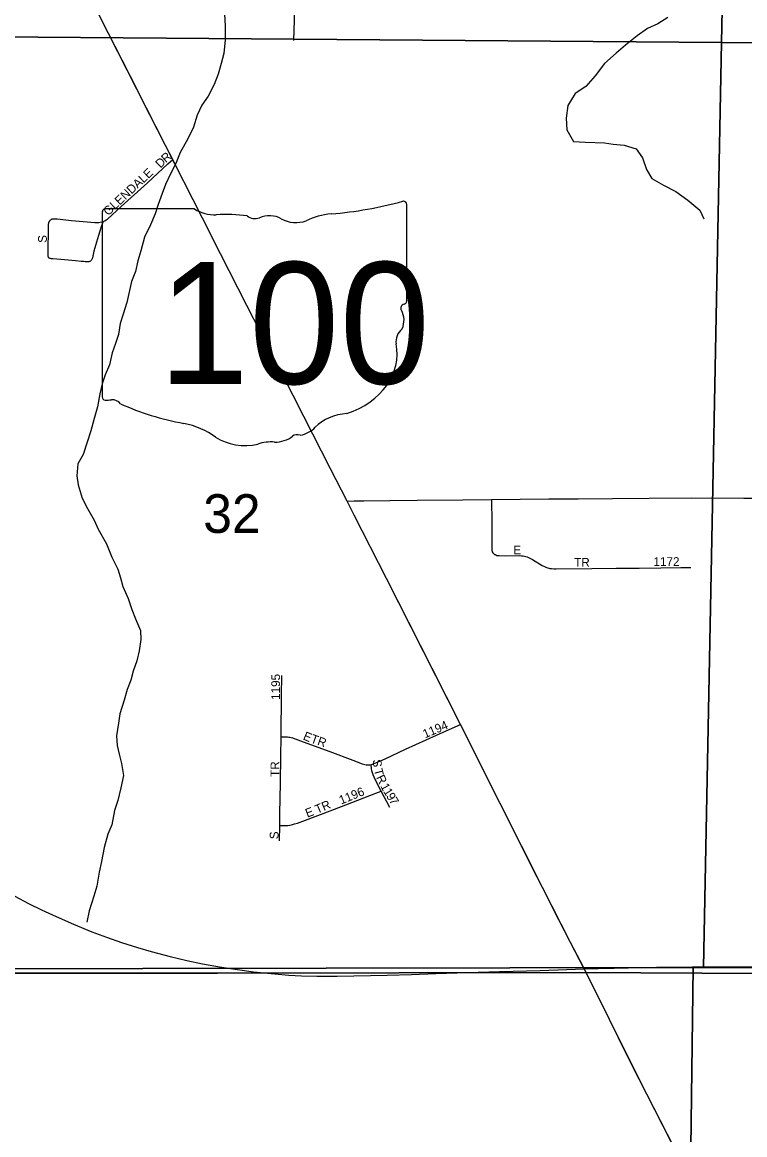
# Model space of a CAD drawing. Extents: x 0 to 34, y 0 to 22.
# Drawn here: x 6.114 to 6.505, y 17.325 to 17.927 of the extents above; entities that cross this region are included whole.
import ezdxf

# ---------------------------------------------------------------- set-up
doc = ezdxf.new("R2010")
doc.units = 0
for name, color, linetype in [('Default', 7, 'Continuous'), ('GM_X_Minor_River', 7, 'Continuous'), ('GM_X_Section', 7, 'Continuous'), ('GM_X_Section_Text', 7, 'Continuous'), ('GM_X_State_Location', 7, 'Continuous'), ('GM_X_State_Route', 7, 'Continuous'), ('GM_X_State_Shield', 7, 'Continuous'), ('GM_X_Township', 7, 'Continuous'), ('GM_X_Township_Road', 7, 'Continuous'), ('GM_X_Township_Subdivision', 7, 'Continuous'), ('GM_X_Township_Subdivision_Text', 7, 'Continuous'), ('GM_X_US_Route', 7, 'Continuous')]:
    doc.layers.add(name, color=color, linetype=linetype)

msp = doc.modelspace()

# ---------------------------------------------------------------- linework, layer by layer
at = {"layer": 'Default'}
for points in [[(6.21175, 17.82109), (6.19182, 17.86034), (6.14526, 17.95216), (6.11969, 18.00306), (6.11076, 18.02099), (6.07084, 18.10026), (6.06147, 18.11896), (6.05496, 18.13197), (6.04884, 18.14072), (6.02545, 18.17135), (6.01014, 18.19175), (5.98748, 18.22193), (5.95849, 18.26057), (5.9573, 18.26217)], [(6.39588, 17.45861), (6.37293, 17.50419), (6.35143, 17.54696), (6.31143, 17.62597), (6.29397, 17.66031), (6.29011, 17.66789), (6.28111, 17.68542), (6.26671, 17.71362)], [(6.41797, 17.41555), (6.41103, 17.42887), (6.39588, 17.45861)], [(6.4784, 17.29558), (6.45232, 17.34668), (6.43203, 17.38715), (6.42213, 17.40718), (6.41883, 17.41387)]]:
    msp.add_lwpolyline(points, dxfattribs=at)
at = {"layer": 'GM_X_Minor_River'}
for points in [[(6.2237, 17.93172), (6.22403, 17.92508), (6.22398, 17.91768), (6.22335, 17.91029), (6.22198, 17.9048), (6.22024, 17.89912), (6.21811, 17.89344), (6.21484, 17.8872), (6.21139, 17.8823), (6.20888, 17.87681), (6.20693, 17.87038), (6.20385, 17.86395), (6.19963, 17.85658), (6.19731, 17.85072), (6.19442, 17.84505), (6.19172, 17.83937), (6.18998, 17.83445), (6.18785, 17.8284), (6.1861, 17.82348), (6.18359, 17.81743), (6.18032, 17.81081), (6.17837, 17.80343), (6.17681, 17.79794), (6.17544, 17.79225), (6.17331, 17.78677), (6.17194, 17.78033), (6.17076, 17.7754), (6.16882, 17.76916), (6.16727, 17.76405), (6.16627, 17.75817), (6.16472, 17.75325), (6.16298, 17.74814), (6.16141, 17.7417), (6.15909, 17.73622), (6.15754, 17.7313), (6.15617, 17.72599), (6.15498, 17.71898), (6.15323, 17.71255), (6.15128, 17.70592), (6.14934, 17.69986), (6.14721, 17.69305), (6.14432, 17.68814), (6.14371, 17.6815), (6.14443, 17.67675), (6.14666, 17.66953), (6.14946, 17.66381), (6.15321, 17.65752), (6.15526, 17.65276), (6.15976, 17.64476), (6.16274, 17.63753), (6.16592, 17.63105), (6.1674, 17.6263), (6.16869, 17.62155), (6.17149, 17.61508), (6.17354, 17.60918), (6.17559, 17.60404), (6.1782, 17.59776), (6.17835, 17.59301), (6.17755, 17.58676), (6.17618, 17.58146), (6.17424, 17.57578), (6.17307, 17.57086), (6.17094, 17.56594), (6.16938, 17.56007), (6.16705, 17.55269), (6.16626, 17.54757), (6.16526, 17.54075), (6.1656, 17.53562)], [(6.4637, 17.92973), (6.45836, 17.92635), (6.45265, 17.92374), (6.44712, 17.9198), (6.44082, 17.91472), (6.43567, 17.91039), (6.42936, 17.90475), (6.42438, 17.89815), (6.41922, 17.8923), (6.4135, 17.88855), (6.40947, 17.88213), (6.40866, 17.87531), (6.40899, 17.86885), (6.41255, 17.86256), (6.41919, 17.86232), (6.42943, 17.86187), (6.43417, 17.86107), (6.44005, 17.86065), (6.44648, 17.8587), (6.45005, 17.85374), (6.45209, 17.84747), (6.45509, 17.84251), (6.46133, 17.83886), (6.46795, 17.83558), (6.47455, 17.83079), (6.48096, 17.82543), (6.48321, 17.82067)], [(6.1656, 17.53562), (6.1667, 17.53087), (6.16799, 17.52574), (6.16909, 17.51928), (6.16752, 17.51265), (6.16595, 17.50584), (6.1642, 17.50035), (6.16263, 17.49258), (6.1605, 17.48747), (6.15855, 17.48028), (6.15717, 17.4727), (6.1558, 17.46702), (6.15461, 17.45944), (6.15305, 17.45395), (6.15052, 17.446), (6.14915, 17.43994)]]:
    msp.add_lwpolyline(points, dxfattribs=at)
at = {"layer": 'GM_X_Section'}
for points in [[(6.50305, 18.41943), (6.4928, 17.91626), (5.98372, 17.92012), (5.99052, 18.41894)], [(6.99984, 18.41775), (6.98884, 17.91553), (6.4928, 17.91626), (6.50305, 18.41943)], [(5.98372, 17.92012), (6.4928, 17.91626), (6.48295, 17.41537), (6.47745, 17.41541), (5.98065, 17.41444), (5.97819, 17.41427)], [(6.98884, 17.91553), (6.97935, 17.41426), (6.48295, 17.41537), (6.4928, 17.91626)], [(5.98065, 17.41444), (6.47745, 17.41541), (6.47069, 16.89897), (6.35343, 16.90099), (6.35585, 17.07131), (5.97596, 17.07021)], [(6.47745, 17.41541), (6.48295, 17.41537), (6.97935, 17.41426), (6.97584, 16.9012), (6.47069, 16.89897)]]:
    msp.add_lwpolyline(points, close=True, dxfattribs=at)
at = {"layer": 'GM_X_State_Route'}
for points in [[(6.19182, 17.86034), (6.18336, 17.87709), (6.17266, 17.89814), (6.16834, 17.90664), (6.1572, 17.92853), (6.15186, 17.93906), (6.14526, 17.95216), (6.13993, 17.96261), (6.13086, 17.98053), (6.11969, 18.00306)], [(6.29397, 17.66031), (6.29011, 17.66789), (6.28111, 17.68542), (6.26671, 17.71362), (6.26087, 17.72497), (6.25239, 17.74149), (6.2431, 17.75942), (6.23577, 17.77381), (6.22146, 17.80177), (6.21175, 17.82109), (6.20179, 17.84066), (6.19565, 17.85276), (6.19249, 17.859), (6.19182, 17.86034)], [(6.39588, 17.45861), (6.39013, 17.4699), (6.38338, 17.48338), (6.37293, 17.50419), (6.36462, 17.52063), (6.35143, 17.54696), (6.33607, 17.57729), (6.32348, 17.60212), (6.31143, 17.62597), (6.29397, 17.66031)], [(6.41845, 17.41462), (6.41103, 17.42887), (6.40469, 17.4412), (6.39712, 17.45616), (6.39588, 17.45861)], [(6.44406, 17.363), (6.44165, 17.36775), (6.43203, 17.38715), (6.42213, 17.40718), (6.41845, 17.41462)], [(6.46989, 17.31238), (6.45232, 17.34668), (6.44406, 17.363)]]:
    msp.add_lwpolyline(points, dxfattribs=at)
at = {"layer": 'GM_X_State_Shield'}
for p, q in [((6.20743, 17.82607), (6.15917, 17.82607)), ((6.32234, 17.7762), (6.32234, 17.82855)), ((6.15754, 17.82434), (6.15754, 17.72428)), ((6.32232, 17.77622), (6.32234, 17.7762))]:
    msp.add_line(p, q, dxfattribs=at)
for centre, major_axis, start_param, end_param in [((6.15943, 17.82456), (0.00191, 0), 1.712693, 3.28349), ((6.21892, 17.83768), (0.01852, 0), 4.042523, 4.731795), ((6.26363, 17.96248), (0.17476, 0), 4.814394, 5.042369), ((6.32051, 17.82876), (0.00183, 0), 6.141152, 7.989035), ((6.22506, 17.76989), (0.06648, 0), 1.404758, 1.657858), ((6.24015, 17.82508), (0.00534, 0), 3.836095, 5.185415), ((6.24799, 17.81351), (0.01111, 0), 0.950623, 2.079405), ((6.26233, 17.82937), (0.01336, 0), 4.081561, 5.145723), ((6.28593, 17.79551), (0.03516, 0), 1.699011, 2.107814), ((6.32191, 17.77236), (0.00284, 0), 1.883978, 3.671073), ((6.30385, 17.76574), (0.01704, 0), 5.934695, 6.695948), ((6.32038, 17.776), (0.00196, 0), 5.05454, 6.418171), ((6.32891, 17.7543), (0.0124, 0), 2.387724, 3.262537), ((6.27342, 17.74764), (0.04371, 0), 5.101752, 6.440018), ((6.15945, 17.72407), (0.00193, 0), 3.00124, 4.508301), ((6.15974, 17.7343), (0.0147, 0), 4.665946, 4.897461), ((6.16275, 17.71851), (0.0053, 0), 0.519207, 1.627899), ((6.22966, 17.80841), (0.1262, 0), 4.195997, 4.488961), ((6.29185, 17.69619), (0.02394, 0), 1.647645, 2.488434), ((6.19204, 17.67933), (0.03949, 0), 0.823519, 1.323587), ((6.26152, 17.71459), (0.01412, 0), 4.937069, 5.64225), ((6.23474, 17.71802), (0.02506, 0), 4.026481, 4.996735), ((6.24922, 17.68342), (0.02059, 0), 1.495662, 1.94098), ((6.25105, 17.71052), (0.01335, 0), 4.691044, 5.507374), ((6.26313, 17.70083), (0.00376, 0), 1.147584, 2.315152)]:
    msp.add_ellipse(centre, major_axis=major_axis, ratio=0.8, start_param=start_param, end_param=end_param, dxfattribs=at)
at = {"layer": 'GM_X_Township'}
for points in [[(6.97838, 17.41123), (6.85112, 17.41144), (6.74587, 17.41079), (6.41604, 17.41268), (6.21985, 17.41235), (5.85482, 17.41232), (5.46352, 17.41199), (5.46485, 17.53523), (5.46518, 17.63837), (5.46592, 17.82417), (5.46606, 17.86097), (5.46575, 18.22108), (5.4678, 18.39922), (5.46813, 18.42722), (5.46918, 18.51868), (5.46955, 18.55069), (5.47024, 18.61055), (5.47055, 18.63752), (5.47095, 18.67198), (5.47122, 18.69589), (5.47192, 18.75628), (5.47212, 18.77357), (5.47293, 18.84412), (5.47565, 19.08008)], [(5.45812, 16.85635), (5.46352, 17.41199), (5.85482, 17.41232), (6.21985, 17.41235), (6.41604, 17.41268), (6.74587, 17.41079), (6.85112, 17.41144), (6.97838, 17.41123), (7.4791, 17.40579), (7.48595, 17.40578), (7.97617, 17.40455), (7.9915, 17.4046), (8.4927, 17.4064), (8.48897, 16.91291)]]:
    msp.add_lwpolyline(points, dxfattribs=at)
at = {"layer": 'GM_X_Township_Road'}
for points in [[(6.29912, 17.66803), (6.31318, 17.66824), (6.32816, 17.66837), (6.35258, 17.66863), (6.36818, 17.66874)], [(6.36818, 17.66874), (6.38374, 17.66895), (6.39928, 17.66904), (6.4152, 17.66915), (6.43382, 17.66929), (6.45362, 17.66951), (6.47653, 17.66956), (6.50486, 17.66946), (6.52181, 17.66939), (6.53767, 17.66933)], [(6.29011, 17.66789), (6.29395, 17.66795), (6.29912, 17.66803)]]:
    msp.add_lwpolyline(points, dxfattribs=at)
at = {"layer": 'GM_X_Township_Subdivision'}
for points in [[(6.26126, 17.91735), (6.2616, 17.92828), (6.26169, 17.93451), (6.26163, 17.93671), (6.26155, 17.93791), (6.26138, 17.93914), (6.26101, 17.94115), (6.2606, 17.94313), (6.26006, 17.94539), (6.25961, 17.94732), (6.25912, 17.94927), (6.25696, 17.95739), (6.25498, 17.96488), (6.25455, 17.96685), (6.2543, 17.96819), (6.25414, 17.96957), (6.25403, 17.97093), (6.25393, 17.9724), (6.25394, 17.9737), (6.2542, 17.98263)], [(6.15794, 17.81925), (6.15717, 17.8169), (6.15623, 17.81406), (6.15548, 17.81168), (6.15433, 17.80802), (6.15347, 17.8051), (6.15295, 17.80318), (6.15253, 17.80133), (6.15221, 17.79959), (6.15213, 17.79927), (6.15203, 17.799), (6.15192, 17.79877), (6.15178, 17.79852), (6.15155, 17.79823), (6.15118, 17.79788), (6.15087, 17.79768), (6.15058, 17.79757), (6.15031, 17.7975), (6.14975, 17.79744), (6.14907, 17.79742), (6.14836, 17.79746), (6.14742, 17.79755), (6.14619, 17.79767), (6.14296, 17.79795), (6.13514, 17.79865), (6.13071, 17.79902), (6.13007, 17.79908), (6.1295, 17.79917), (6.12913, 17.79927), (6.12897, 17.79934), (6.12881, 17.79943), (6.12868, 17.79954), (6.12857, 17.79966), (6.12846, 17.79983), (6.12837, 17.79999), (6.12828, 17.80025), (6.12824, 17.80054), (6.1282, 17.80098), (6.12818, 17.80145), (6.12819, 17.80231), (6.12829, 17.80652), (6.1284, 17.81192), (6.1284, 17.8169), (6.12842, 17.81755), (6.12847, 17.81809), (6.12852, 17.81835), (6.12859, 17.8186), (6.12867, 17.81883), (6.12877, 17.81906), (6.12888, 17.81926), (6.12901, 17.81947), (6.12917, 17.81967), (6.12938, 17.81992), (6.12963, 17.82017), (6.12984, 17.82033), (6.13003, 17.82047), (6.1302, 17.82058), (6.13045, 17.82068), (6.13072, 17.82074), (6.13098, 17.82076), (6.13156, 17.8208), (6.13221, 17.82078), (6.13304, 17.82072), (6.1409, 17.8199), (6.1536, 17.81871), (6.15471, 17.81871), (6.15574, 17.81879), (6.15648, 17.81888), (6.15722, 17.81904), (6.15794, 17.81925), (6.15899, 17.8197), (6.15969, 17.82011), (6.16034, 17.8206), (6.16774, 17.82731), (6.18201, 17.84022), (6.19311, 17.85042), (6.19565, 17.85276)], [(6.36818, 17.66874), (6.36835, 17.65607), (6.36834, 17.64314), (6.36836, 17.64197), (6.36842, 17.64135), (6.36852, 17.64081), (6.36867, 17.64036), (6.36889, 17.63995), (6.3691, 17.63966), (6.36946, 17.6393), (6.36984, 17.63905), (6.3702, 17.63888), (6.37056, 17.63872), (6.37119, 17.63851), (6.37176, 17.63841), (6.37238, 17.63835), (6.37604, 17.63831), (6.38343, 17.63836), (6.3844, 17.63831), (6.38487, 17.63827), (6.38529, 17.63823), (6.38602, 17.63809), (6.38678, 17.63788), (6.38761, 17.63761), (6.38854, 17.63724), (6.38929, 17.63685), (6.39045, 17.6362), (6.39574, 17.63307), (6.39734, 17.63229), (6.39804, 17.63196), (6.39882, 17.63167), (6.39973, 17.63143), (6.40063, 17.6313), (6.40199, 17.63122), (6.40322, 17.63122), (6.42262, 17.63143), (6.43568, 17.63148), (6.44811, 17.6316), (6.45995, 17.63173), (6.47078, 17.63186), (6.47609, 17.63186)], [(6.25432, 17.54027), (6.25434, 17.54148), (6.25456, 17.56261), (6.25468, 17.57347)], [(6.30308, 17.52522), (6.30378, 17.52544), (6.30456, 17.52573), (6.30569, 17.52619), (6.31065, 17.52841), (6.32175, 17.53351), (6.33852, 17.54108), (6.34863, 17.54569), (6.35143, 17.54696)], [(6.25361, 17.49222), (6.2537, 17.49855), (6.25396, 17.51533), (6.25412, 17.52968), (6.25432, 17.54027)], [(6.25432, 17.54027), (6.25612, 17.54027), (6.2571, 17.54027), (6.25782, 17.54022), (6.25847, 17.54013), (6.25914, 17.54001), (6.25979, 17.53985), (6.2605, 17.53964), (6.2663, 17.53759), (6.28069, 17.53221), (6.29318, 17.52751), (6.29815, 17.52566), (6.2989, 17.52543), (6.2997, 17.52522), (6.30036, 17.52512), (6.301, 17.52506), (6.30169, 17.52506), (6.30232, 17.52512), (6.30308, 17.52522)], [(6.30845, 17.51084), (6.3052, 17.51716), (6.30413, 17.51972), (6.30374, 17.52075), (6.3035, 17.52178), (6.30332, 17.52297), (6.30308, 17.52522)], [(6.25361, 17.49222), (6.25605, 17.49222), (6.2579, 17.4923), (6.25906, 17.49242), (6.26002, 17.4926), (6.26164, 17.49304), (6.26321, 17.49357), (6.27708, 17.49872), (6.28932, 17.50341), (6.30564, 17.50975), (6.30845, 17.51084)], [(6.3132, 17.50188), (6.30845, 17.51084)], [(6.25343, 17.48387), (6.25361, 17.49222)]]:
    msp.add_lwpolyline(points, dxfattribs=at)
at = {"layer": 'GM_X_US_Route'}
for points in [[(6.11025, 17.45392), (6.11764, 17.44996), (6.12459, 17.44653), (6.13249, 17.4429), (6.14189, 17.43881), (6.15195, 17.43471), (6.15979, 17.43175), (6.16801, 17.42891), (6.17659, 17.42618), (6.18404, 17.42402), (6.19424, 17.42131), (6.2033, 17.41915), (6.21181, 17.41738), (6.22098, 17.41574), (6.2306, 17.41422), (6.23079, 17.41419), (6.23941, 17.41306), (6.24898, 17.41205), (6.25857, 17.41127), (6.26539, 17.4109), (6.27377, 17.41068), (6.28463, 17.4107), (6.31167, 17.4112), (6.32502, 17.41162), (6.33818, 17.41206), (6.37256, 17.41315), (6.39463, 17.41378), (6.41845, 17.41462)], [(6.42595, 17.41479), (6.43463, 17.41499), (6.4576, 17.41552), (6.46094, 17.41556)], [(6.46094, 17.41556), (6.47686, 17.41578), (6.51384, 17.41581), (6.53963, 17.41577), (6.56915, 17.41564), (6.60705, 17.4154), (6.62383, 17.41529), (6.67075, 17.41513), (6.73891, 17.41466), (6.76647, 17.41461), (6.79101, 17.41442)], [(6.41845, 17.41462), (6.42595, 17.41479)]]:
    msp.add_lwpolyline(points, dxfattribs=at)

# ---------------------------------------------------------------- texts
at = {"layer": 'GM_X_Section_Text'}
msp.add_text('32', height=0.020928, rotation=0.00001, dxfattribs=at).set_placement((6.21216, 17.65066))
at = {"layer": 'GM_X_State_Location'}
for s in ['s', 'r']:
    msp.add_text(s, height=0.0000947, dxfattribs=at).set_placement((6.23809, 17.76766))
msp.add_text('100', height=0.0000947, rotation=0.00001, dxfattribs=at).set_placement((6.20466, 17.76077))
at = {"layer": 'GM_X_State_Shield'}
msp.add_text('100', height=0.065918, dxfattribs=at).set_placement((6.1879, 17.73134))
at = {"layer": 'GM_X_Township_Subdivision_Text'}
for s, height, rotation, p in [('R', 0.00473, 41.32298, (6.19195, 17.85079)), ('D', 0.00473, 44.36632, (6.18902, 17.84792)), ('GLENDALE', 0.004735, 42.8388, (6.16071, 17.82211)), ('S', 0.00473, 90, (6.12752, 17.80771)), ('E', 0.00473, 0.00001, (6.38007, 17.63902)), ('TR', 0.004735, 0.00001, (6.41299, 17.63235)), ('1172', 0.004735, 0.00001, (6.45591, 17.63277)), ('1195', 0.004735, 90, (6.25377, 17.56022)), ('1194', 0.004735, 22.93374, (6.33222, 17.53936)), ('E', 0.00473, 336.81272, (6.26584, 17.53894)), ('TR', 0.004735, 340.56804, (6.26995, 17.5373)), ('TR', 0.004735, 90, (6.25335, 17.51855)), ('S', 0.00473, 275.41703, (6.30388, 17.52779)), ('T', 0.00473, 284.79952, (6.30448, 17.5224)), ('R', 0.00473, 295.49816, (6.30567, 17.51827)), ('1196', 0.004735, 22.16248, (6.28684, 17.50354)), ('1', 0.00473, 297.67942, (6.30794, 17.5136)), ('1', 0.00473, 301.43525, (6.30946, 17.51072)), ('TR', 0.004735, 22.93429, (6.2739, 17.49853)), ('9', 0.00473, 302.2141, (6.31102, 17.50817)), ('7', 0.00473, 302.27299, (6.31258, 17.5057)), ('E', 0.00473, 20.56203, (6.26851, 17.49646)), ('S', 0.00473, 90, (6.25293, 17.4848))]:
    msp.add_text(s, height=height, rotation=rotation, dxfattribs=at).set_placement(p)

doc.saveas('drawing.dxf')
